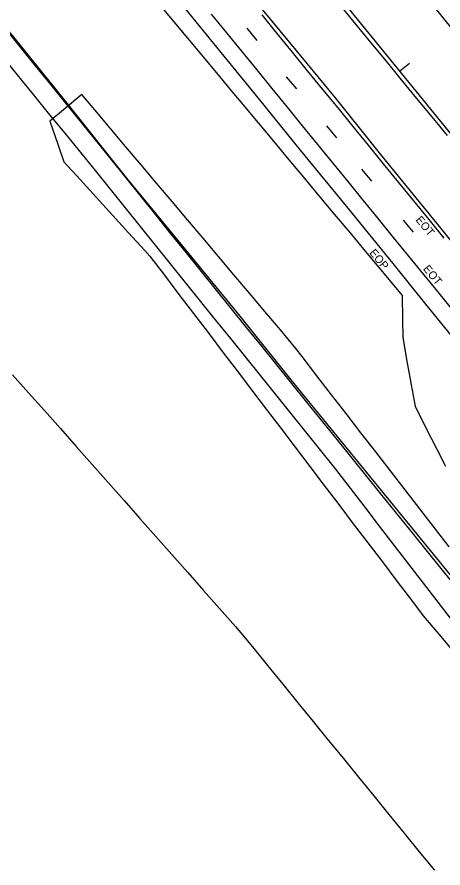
# Model space of a CAD drawing. Extents: x 2132221 to 2141942, y 535736 to 547298.
# Drawn here: x 2139996 to 2140262, y 537530 to 538062 of the extents above; entities that cross this region are included whole.
import ezdxf

# ---------------------------------------------------------------- set-up
doc = ezdxf.new("R2010")
doc.units = 0
for name, color, linetype in [('RD_EX_Driveway', 7, 'Continuous'), ('RD_EX_Fence_Other', 7, 'Continuous'), ('RD_EX_GuardRail', 7, 'Continuous'), ('RD_EX_Misc', 7, 'Continuous'), ('RD_EX_Misc_txCode', 7, 'Continuous'), ('RD_EX_Road', 7, 'Continuous'), ('RD_EX_Road_txCode', 7, 'Continuous'), ('RD_EX_VEG', 7, 'Continuous'), ('RD_HC_Cl', 7, 'Continuous'), ('RD_HC_Data_Tic', 7, 'Continuous'), ('TOPO_E_TLIML-Line', 7, 'Continuous')]:
    doc.layers.add(name, color=color, linetype=linetype)

msp = doc.modelspace()

# ---------------------------------------------------------------- linework, layer by layer
at = {"layer": 'RD_EX_Driveway'}
for points in [[(2139988.67, 538054.61), (2139998.09, 538042.93), (2140007.5, 538031.26), (2140016.92, 538019.58), (2140026.33, 538007.91), (2140054.58, 537972.89), (2140064, 537961.21), (2140073.41, 537949.54), (2140082.83, 537937.87), (2140092.24, 537926.19), (2140101.66, 537914.52), (2140129.91, 537879.49), (2140139.32, 537867.82), (2140148.74, 537856.15), (2140158.16, 537844.47), (2140167.57, 537832.8), (2140176.99, 537821.12), (2140195.82, 537797.77), (2140205.23, 537786.1), (2140224.07, 537762.75), (2140242.9, 537739.4), (2140252.31, 537727.73), (2140261.73, 537716.06), (2140271.14, 537704.38)], [(2140268.25, 537684.22), (2140259.12, 537696.1), (2140249.99, 537707.97), (2140240.86, 537719.85), (2140231.73, 537731.72), (2140222.61, 537743.6), (2140213.48, 537755.47), (2140204.35, 537767.35), (2140195.22, 537779.22), (2140185.87, 537790.93), (2140176.48, 537802.6), (2140167.1, 537814.27), (2140157.71, 537825.94), (2140138.93, 537849.28), (2140129.54, 537860.95), (2140120.15, 537872.62), (2140101.38, 537895.96), (2140091.99, 537907.63), (2140082.6, 537919.3), (2140073.21, 537930.97), (2140054.44, 537954.31), (2140045.04, 537965.97), (2140026.08, 537989.17), (2140016.6, 538000.76), (2140007.12, 538012.36), (2139988.16, 538035.55)]]:
    msp.add_lwpolyline(points, dxfattribs=at)
at = {"layer": 'RD_EX_Fence_Other'}
msp.add_line((2140167.14, 537835.13), (2140668.17, 537219.94), dxfattribs=at)
msp.add_lwpolyline([(2139889.51, 538176.89), (2139922.4, 538136.45), (2139953.27, 538098.52), (2139994.03, 538049.06), (2140025.49, 538009.95), (2140064.51, 537961.16), (2140091.65, 537928.04), (2140133.56, 537877.03), (2140167.14, 537835.13)], dxfattribs=at)
at = {"layer": 'RD_EX_GuardRail'}
msp.add_lwpolyline([(2140264.89, 537987.71), (2140255.38, 537999.31), (2140245.86, 538010.9), (2140236.35, 538022.5), (2140226.83, 538034.09), (2140217.31, 538045.69), (2140207.8, 538057.28), (2140198.28, 538068.87)], dxfattribs=at)
at = {"layer": 'RD_EX_Misc'}
for p, q in [((2140139.57, 538054.74), (2140145.86, 538047.21)), ((2140164.29, 538024.34), (2140170.59, 538016.82)), ((2140189.33, 537993.73), (2140195.63, 537986.21)), ((2140211.27, 537966.7), (2140217.57, 537959.17)), ((2140237.25, 537934.83), (2140243.55, 537927.31))]:
    msp.add_line(p, q, dxfattribs=at)
for points in [[(2140269.21, 537877.53), (2140259.74, 537889.16), (2140250.27, 537900.8), (2140240.79, 537912.43), (2140231.32, 537924.06), (2140221.85, 537935.69), (2140212.38, 537947.32), (2140202.9, 537958.95), (2140193.43, 537970.58), (2140183.96, 537982.21), (2140174.49, 537993.84), (2140165.01, 538005.47), (2140155.54, 538017.1), (2140146.07, 538028.73), (2140136.6, 538040.36), (2140127.12, 538051.99), (2140117.65, 538063.62)], [(2140148.97, 538063.05), (2140158.45, 538051.43), (2140167.94, 538039.8), (2140177.42, 538028.18), (2140186.9, 538016.56), (2140196.38, 538004.94), (2140205.86, 537993.31), (2140215.35, 537981.69), (2140224.83, 537970.07), (2140234.31, 537958.45), (2140243.79, 537946.82), (2140253.28, 537935.2), (2140262.76, 537923.58)]]:
    msp.add_lwpolyline(points, dxfattribs=at)
at = {"layer": 'RD_EX_Road'}
for points in [[(2139921.79, 538480), (2139946.02, 538450.34), (2139974.1, 538415.49), (2139997.12, 538387.16), (2140017.9, 538361.65), (2140039.96, 538334.4), (2140063.9, 538304.87), (2140087.44, 538275.84), (2140111.59, 538246.38), (2140136.82, 538215.31), (2140158.07, 538189.6), (2140178.39, 538164.11), (2140199.95, 538138.01), (2140232.94, 538097.16), (2140248.09, 538078.69), (2140269.53, 538052.05), (2140291.12, 538025.3), (2140312.85, 537998.52), (2140333.22, 537973.82), (2140353.82, 537948.47), (2140374.86, 537922.74), (2140401.79, 537889.76)], [(2139857.97, 538425.22), (2139881.25, 538396.49), (2139906.86, 538364.69), (2139936.98, 538327.43), (2139965.41, 538293.27), (2139992.83, 538259.43), (2140029.94, 538213.8), (2140070.83, 538163.2), (2140102.23, 538124.59), (2140136.12, 538082.6), (2140166.33, 538045.8), (2140194.75, 538011.29), (2140224.05, 537974.8), (2140258.2, 537933.02), (2140289.5, 537894.16), (2140331.4, 537842.81)], [(2139821.34, 538407.52), (2139844.07, 538380.28), (2139869.36, 538350.15), (2139893.18, 538321.68), (2139922.97, 538286.25), (2139948.19, 538255.39), (2139971.24, 538227.13), (2139997.6, 538194.42), (2140020.91, 538165.54), (2140045.38, 538135.86), (2140069.13, 538106.42), (2140093.97, 538075.81), (2140118.85, 538045.18), (2140147.52, 538010.04), (2140173.04, 537978.51), (2140202.74, 537942.39), (2140230.85, 537907.67), (2140252.16, 537881.37), (2140277.92, 537849.66), (2140308.18, 537812.91)]]:
    msp.add_lwpolyline(points, dxfattribs=at)
at = {"layer": 'RD_EX_VEG'}
for points in [[(2140082.34, 538072.89), (2140091.94, 538061.36), (2140101.55, 538049.84), (2140111.15, 538038.32), (2140120.75, 538026.8), (2140130.36, 538015.28), (2140137.1, 538007.18), (2140146.71, 537995.66), (2140156.31, 537984.14), (2140165.92, 537972.62), (2140175.08, 537961.62), (2140184.68, 537950.1), (2140194.29, 537938.58), (2140203.89, 537927.05), (2140213.5, 537915.53), (2140223.1, 537904.01), (2140232.7, 537892.49), (2140236.69, 537887.7), (2140236.87, 537872.7), (2140237, 537861.55), (2140239.65, 537846.79), (2140242.31, 537832.02), (2140244.74, 537818.53), (2140251.52, 537805.15), (2140258.31, 537791.77), (2140263.71, 537781.12)], [(2140265.95, 537730.81), (2140256.78, 537742.68), (2140247.62, 537754.56), (2140238.45, 537766.43), (2140229.29, 537778.3), (2140220.12, 537790.18), (2140210.95, 537802.05), (2140201.79, 537813.93), (2140192.62, 537825.8), (2140183.46, 537837.67), (2140174.29, 537849.55), (2140170.27, 537854.75), (2140160.6, 537866.22), (2140150.94, 537877.69), (2140141.27, 537889.16), (2140131.6, 537900.63), (2140121.94, 537912.1), (2140112.27, 537923.57), (2140102.6, 537935.04), (2140092.94, 537946.51), (2140083.27, 537957.98), (2140073.6, 537969.45), (2140063.93, 537980.92), (2140054.27, 537992.39), (2140044.6, 538003.86), (2140036.57, 538013.39), (2140025.1, 538003.72), (2140016.65, 537996.6), (2140021.53, 537982.42), (2140025.35, 537971.3), (2140035.46, 537960.22), (2140045.57, 537949.14), (2140055.68, 537938.06), (2140065.79, 537926.98), (2140075.9, 537915.89), (2140079.1, 537912.38), (2140088.18, 537900.44), (2140097.25, 537888.49), (2140106.33, 537876.55), (2140115.4, 537864.61), (2140124.48, 537852.66), (2140133.55, 537840.72), (2140142.63, 537828.78), (2140151.7, 537816.83), (2140160.78, 537804.89), (2140169.85, 537792.95), (2140178.93, 537781), (2140188, 537769.06), (2140197.08, 537757.11), (2140206.15, 537745.17), (2140215.23, 537733.23), (2140224.3, 537721.28), (2140233.38, 537709.34), (2140242.45, 537697.4), (2140249.88, 537687.62), (2140259.54, 537676.14), (2140269.19, 537664.66)]]:
    msp.add_lwpolyline(points, dxfattribs=at)
at = {"layer": 'RD_HC_Cl'}
msp.add_line((2136971.61, 542041.65), (2141699.63, 536226.46), dxfattribs=at)
msp.add_arc((2150022.65, 545440.3), 12130.51, 215.140721, 218.874533, dxfattribs=at)
at = {"layer": 'RD_HC_Data_Tic'}
msp.add_line((2140235.01, 538027.86), (2140241.22, 538032.91), dxfattribs=at)
at = {"layer": 'TOPO_E_TLIML-Line'}
msp.add_lwpolyline([(2139993.32, 537838.29), (2140003.26, 537827.05), (2140013.2, 537815.82), (2140023.14, 537804.59), (2140033.09, 537793.36), (2140043.03, 537782.13), (2140052.97, 537770.89), (2140062.91, 537759.66), (2140072.85, 537748.43), (2140082.79, 537737.2), (2140092.74, 537725.96), (2140102.68, 537714.73), (2140112.62, 537703.5), (2140122.56, 537692.27), (2140132.5, 537681.03), (2140133.61, 537679.78), (2140143.09, 537668.15), (2140152.56, 537656.52), (2140162.04, 537644.89), (2140171.52, 537633.26), (2140180.99, 537621.64), (2140190.47, 537610.01), (2140199.94, 537598.38), (2140209.42, 537586.75), (2140218.89, 537575.12), (2140228.37, 537563.49), (2140237.84, 537551.87), (2140247.32, 537540.24), (2140256.79, 537528.61)], dxfattribs=at)

# ---------------------------------------------------------------- texts
at = {"layer": 'RD_EX_Misc_txCode'}
for p in [(2140244.74, 537934.9), (2140249.44, 537904.28)]:
    msp.add_text('EOT', height=5, rotation=309.5103, dxfattribs=at).set_placement(p)
at = {"layer": 'RD_EX_Road_txCode'}
msp.add_text('EOP', height=5, rotation=309.5103, dxfattribs=at).set_placement((2140215.89, 537914.31))

doc.saveas('drawing.dxf')
